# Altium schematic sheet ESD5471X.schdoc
size 127 x 101 mm
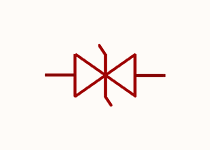
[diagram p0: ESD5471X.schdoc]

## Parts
D?  esd5471x  [DFN1006-2L_L1.0-W0.6-P0.70-BI]  (value not drawn)

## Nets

Not connected (* = marked no-connect by the designer): D? 1 2

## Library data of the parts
D? = esd5471x: 极性:双向;反向截止电压(Vrwm):5V;最大钳位电压:17V;峰值脉冲电流(Ipp):7A;峰值脉冲功率(Ppp):75W;击穿电压:5.6V;; Manufacturer: TECH PUBLIC(台舟); AddInBom: yes; ModelId: 8799f5d6b8214f9296437c35b5df300c; ModelName: DFN1006-2L_L1.0-W0.6-H0.5; ModelTransform: 39.37,23.622,0,0,0,0,0,0,0; polarity: 双向; Reverse Stand-Off Voltage (Vrwm): 5V; Maximum Clamping Voltage: 17V; Peak Pulse Current (Ipp): 7A; Peak Pulse Power Dissipation (Ppp): 75W; Breakdown Voltage: 5.6V; Reverse Leakage Current (Ir): 200nA; Number of Lines: 单路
